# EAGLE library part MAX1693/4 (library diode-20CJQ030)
Maxim's MAX1693/(MAX1693H)/MAX1694 USB Current-Limited Switches with Fault Blanking Description: The MAX1693/(MAX1693H)/MAX1694 are current-limited, 60mOm switches with built-in fault blanking. Their accurate preset current limit of 0.7A to 1.0A makes them ideally suited for USB applications. Their low quiescent supply current (14µA) and shutdown current (1µA) conserve battery power in portable applications. The MAX1693/(MAX1693H)/MAX1694 operate with inputs from 2.7V to 5.5V, making them ideal for both 3V and 5V systems. A fault signal notifies the microprocessor that the internal current limit has been reached. A 10ms fault-blanking feature allows momentary faults (such as those caused when hot-swapping into a capacitive load) to be ignored, thus preventing false alarms to the host system. This fault blanking also prevents a fault signal from being issued when the device is powering up. In the MAX1693/(MAX1693H), an output overcurrent condition causes the switch to current limit at 0.7A to 1.0A and FAULT to go low after the 10ms blanking period. When the overcurrent condition is removed, FAULT returns to its high-impedance state. In the MAX1694, any overcurrent longer than 10ms will latch the switch open and set FAULT low. The latch is cleared by cycling the ON input or by powering up the device again. This feature saves power by preventing the device from thermally cycling on and off in case of a persistent short-circuit condition. The MAX1693/(MAX1693H)/MAX1694 have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
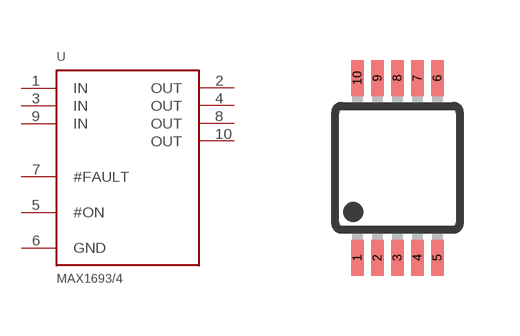
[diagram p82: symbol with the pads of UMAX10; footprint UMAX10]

Designator prefix U

## MAX1693/4  [UMAX10]
1  IN  in
2  OUT  in
3  IN  in
4  OUT  in
5  #ON  in
6  GND  in
7  #FAULT  in
8  OUT  in
9  IN  in
10  OUT  in

## Footprint UMAX10 (pad centres in mm)
micro MAX Package
smd 0.32 x 0.9: 1 -1,-2.25; 2 -0.5,-2.25; 3 0,-2.25; 4 0.5,-2.25; 5 1,-2.25; 6 1,2.25; 7 0.5,2.25; 8 0,2.25; 9 -0.5,2.25; 10 -1,2.25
